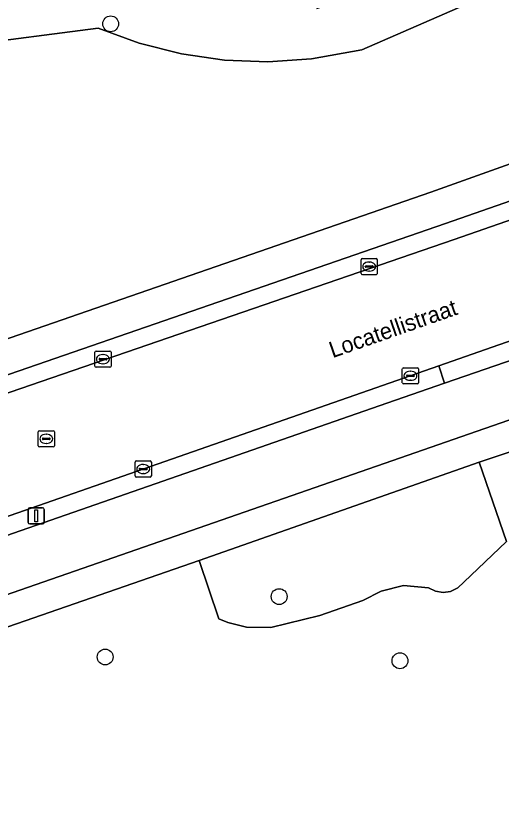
# Model space of a CAD drawing. Extents: x 159817 to 160765, y 380688 to 381638.
# Drawn here: x 160218.82 to 160248.8, y 380832.51 to 380881.05 of the extents above; entities that cross this region are included whole.
import ezdxf

# ---------------------------------------------------------------- set-up
doc = ezdxf.new("R2010")
doc.units = 0
for name, color, linetype in [('IMGEO_Berm_open', 7, 'Continuous'), ('IMGEO_Boom', 7, 'Continuous'), ('IMGEO_Fietspad_gesloten', 7, 'Continuous'), ('IMGEO_Groenvoorziening', 7, 'Continuous'), ('IMGEO_Kolk', 7, 'Continuous'), ('IMGEO_Lichtmast', 7, 'Continuous'), ('IMGEO_Openbare_ruimte_label', 7, 'Continuous'), ('IMGEO_Rijbaan_lokaal_gesloten', 7, 'Continuous'), ('IMGEO_Rioolput', 7, 'Continuous'), ('IMGEO_Voetpad_open', 7, 'Continuous')]:
    doc.layers.add(name, color=color, linetype=linetype)

msp = doc.modelspace()

# ---------------------------------------------------------------- linework, layer by layer
at = {"layer": 'IMGEO_Berm_open'}
for points in [[(160258.032, 380872.366), (160257.939, 380872.612), (160245.35, 380868.231), (160203.278, 380853.707)], [(160208.628, 380854.439), (160245.892, 380867.232), (160259.13, 380871.851)], [(160245.306, 380858.382), (160244.942, 380859.44), (160200.245, 380843.851), (160184.195, 380838.372)], [(160194.251, 380840.623), (160241.26, 380856.971), (160245.306, 380858.382)]]:
    msp.add_lwpolyline(points, dxfattribs=at)
msp.add_lwpolyline([(160252.766, 380860.95), (160252.421, 380862.048), (160244.942, 380859.44), (160245.306, 380858.382)], close=True, dxfattribs=at)
at = {"layer": 'IMGEO_Boom'}
for centre in [(160224.68, 380880.545), (160235.089, 380845.202), (160224.342, 380841.476), (160242.547, 380841.242)]:
    msp.add_circle(centre, 0.489, dxfattribs=at)
at = {"layer": 'IMGEO_Fietspad_gesloten'}
for points in [[(160312.936, 380882.064), (160310.27, 380881.1), (160252.914, 380861.001), (160252.766, 380860.95), (160245.306, 380858.382), (160241.26, 380856.971), (160194.251, 380840.623)], [(160185.448, 380834.002), (160214.797, 380844.116), (160254.484, 380857.89), (160313.244, 380878.473)], [(160257.134, 380874.691), (160244.449, 380870.167), (160212.621, 380859.165), (160209.034, 380857.925), (160202.886, 380855.8), (160196.659, 380853.844)], [(160203.278, 380853.707), (160245.35, 380868.231), (160257.939, 380872.612), (160258.032, 380872.366)]]:
    msp.add_lwpolyline(points, dxfattribs=at)
at = {"layer": 'IMGEO_Groenvoorziening'}
for points in [[(160218.084, 380882.815), (160206.489, 380872.61), (160215.634, 380879.207), (160223.918, 380880.278), (160226.441, 380879.35), (160229.047, 380878.691), (160231.708, 380878.307), (160234.394, 380878.204), (160237.076, 380878.383), (160240.184, 380878.949), (160253.758, 380884.876), (160253.17, 380886.647), (160237.384, 380881.476)], [(160253.758, 380884.876), (160240.184, 380878.949), (160237.076, 380878.383), (160234.394, 380878.204), (160231.708, 380878.307), (160229.047, 380878.691), (160226.441, 380879.35), (160223.918, 380880.278), (160215.634, 380879.207), (160206.489, 380872.61), (160205.888, 380872.081), (160204.881, 380871.517), (160202.436, 380868.022), (160202.535, 380866.772), (160203.004, 380864.973), (160203.836, 380863.311), (160204.996, 380861.858), (160206.432, 380860.678), (160208.082, 380859.822), (160209.874, 380859.328), (160212.621, 380859.165), (160244.449, 380870.167), (160257.134, 380874.691)], [(160254.028, 380855.706), (160247.431, 380853.502), (160249.122, 380848.609), (160246.491, 380846.097), (160246.127, 380845.74), (160245.678, 380845.514), (160245.207, 380845.446), (160244.739, 380845.527), (160244.318, 380845.749), (160242.759, 380845.884), (160241.397, 380845.541), (160240.251, 380844.964), (160237.598, 380844.027), (160234.579, 380843.289), (160233.078, 380843.305), (160231.909, 380843.599), (160231.354, 380843.836), (160230.145, 380847.428), (160187.08, 380832.509)]]:
    msp.add_lwpolyline(points, dxfattribs=at)
msp.add_lwpolyline([(160230.145, 380847.428), (160231.354, 380843.836), (160231.909, 380843.599), (160233.078, 380843.305), (160234.579, 380843.289), (160237.598, 380844.027), (160240.251, 380844.964), (160241.397, 380845.541), (160242.759, 380845.884), (160244.318, 380845.749), (160244.739, 380845.527), (160245.207, 380845.446), (160245.678, 380845.514), (160246.127, 380845.74), (160246.491, 380846.097), (160249.122, 380848.609), (160247.431, 380853.502)], close=True, dxfattribs=at)
at = {"layer": 'IMGEO_Kolk'}
for p, q in [((160240.149, 380865.142), (160240.149, 380865.994)), ((160240.224, 380866.068), (160241.076, 380866.068)), ((160241.15, 380865.994), (160241.15, 380865.142)), ((160240.408, 380865.562), (160240.408, 380865.574)), ((160240.846, 380865.525), (160240.448, 380865.525)), ((160240.451, 380865.611), (160240.849, 380865.611)), ((160240.637, 380865.848), (160240.662, 380865.848)), ((160240.892, 380865.574), (160240.892, 380865.562)), ((160241.076, 380865.068), (160240.224, 380865.068)), ((160240.66, 380865.288), (160240.635, 380865.288)), ((160223.703, 380859.427), (160223.703, 380860.279)), ((160223.778, 380860.353), (160224.63, 380860.353)), ((160224.191, 380860.133), (160224.216, 380860.133)), ((160224.704, 380860.279), (160224.704, 380859.427)), ((160223.962, 380859.847), (160223.962, 380859.859)), ((160224.4, 380859.81), (160224.002, 380859.81)), ((160224.005, 380859.896), (160224.403, 380859.896)), ((160224.446, 380859.859), (160224.446, 380859.847)), ((160224.63, 380859.353), (160223.778, 380859.353)), ((160224.214, 380859.573), (160224.189, 380859.573)), ((160242.694, 380858.403), (160242.694, 380859.255)), ((160242.769, 380859.329), (160243.621, 380859.329)), ((160243.695, 380859.255), (160243.695, 380858.403)), ((160242.953, 380858.823), (160242.953, 380858.835)), ((160243.391, 380858.786), (160242.993, 380858.786)), ((160242.996, 380858.872), (160243.394, 380858.872)), ((160243.182, 380859.109), (160243.207, 380859.109)), ((160243.437, 380858.835), (160243.437, 380858.823)), ((160243.621, 380858.329), (160242.769, 380858.329)), ((160243.205, 380858.549), (160243.18, 380858.549)), ((160226.193, 380852.648), (160226.193, 380853.5)), ((160226.268, 380853.574), (160227.12, 380853.574)), ((160226.681, 380853.354), (160226.706, 380853.354)), ((160227.194, 380853.5), (160227.194, 380852.648)), ((160226.452, 380853.068), (160226.452, 380853.08)), ((160226.89, 380853.031), (160226.492, 380853.031)), ((160226.495, 380853.117), (160226.893, 380853.117)), ((160226.936, 380853.08), (160226.936, 380853.068)), ((160227.12, 380852.574), (160226.268, 380852.574)), ((160226.704, 380852.794), (160226.679, 380852.794))]:
    msp.add_line(p, q, dxfattribs=at)
for points in [[(160240.149, 380865.142), (160240.149, 380865.994)], [(160240.224, 380866.068), (160241.076, 380866.068)], [(160241.15, 380865.994), (160241.15, 380865.142)], [(160241.076, 380865.068), (160240.224, 380865.068)], [(160223.703, 380859.427), (160223.703, 380860.279)], [(160223.778, 380860.353), (160224.63, 380860.353)], [(160224.704, 380860.279), (160224.704, 380859.427)], [(160224.63, 380859.353), (160223.778, 380859.353)], [(160242.694, 380858.403), (160242.694, 380859.255)], [(160242.769, 380859.329), (160243.621, 380859.329)], [(160243.695, 380859.255), (160243.695, 380858.403)], [(160243.621, 380858.329), (160242.769, 380858.329)], [(160226.193, 380852.648), (160226.193, 380853.5)], [(160226.268, 380853.574), (160227.12, 380853.574)], [(160227.194, 380853.5), (160227.194, 380852.648)], [(160227.12, 380852.574), (160226.268, 380852.574)]]:
    msp.add_lwpolyline(points, dxfattribs=at)
for centre, radius, start, end in [((160240.226, 380865.992), 0.0765, 91.552, 178.448), ((160240.226, 380865.992), 0.0765, 91.552, 178.448), ((160241.074, 380865.992), 0.0765, 1.552, 88.448), ((160241.074, 380865.992), 0.0765, 1.552, 88.448), ((160240.448, 380865.571), 0.0403, 85.8775, 175.7526), ((160240.445, 380865.561), 0.0366, 178.938, 274.7102), ((160240.849, 380865.568), 0.043, 264.8664, 352.4533), ((160240.853, 380865.573), 0.0386, 1.7309, 96.639), ((160240.226, 380865.144), 0.0765, 181.552, 268.448), ((160240.226, 380865.144), 0.0765, 181.552, 268.448), ((160241.074, 380865.144), 0.0765, 271.552, 358.448), ((160241.074, 380865.144), 0.0765, 271.552, 358.448), ((160223.78, 380860.277), 0.0765, 91.552, 178.448), ((160223.78, 380860.277), 0.0765, 91.552, 178.448), ((160224.628, 380860.277), 0.0765, 1.552, 88.448), ((160224.628, 380860.277), 0.0765, 1.552, 88.448), ((160224.002, 380859.856), 0.0403, 85.8775, 175.7526), ((160223.999, 380859.846), 0.0366, 178.938, 274.7102), ((160224.403, 380859.853), 0.043, 264.8664, 352.4533), ((160224.407, 380859.858), 0.0386, 1.7309, 96.639), ((160223.78, 380859.429), 0.0765, 181.552, 268.448), ((160223.78, 380859.429), 0.0765, 181.552, 268.448), ((160224.628, 380859.429), 0.0765, 271.552, 358.448), ((160224.628, 380859.429), 0.0765, 271.552, 358.448), ((160242.771, 380859.253), 0.0765, 91.552, 178.448), ((160242.771, 380859.253), 0.0765, 91.552, 178.448), ((160243.619, 380859.253), 0.0765, 1.552, 88.448), ((160243.619, 380859.253), 0.0765, 1.552, 88.448), ((160242.993, 380858.832), 0.0403, 85.8775, 175.7526), ((160242.99, 380858.822), 0.0366, 178.938, 274.7102), ((160243.394, 380858.829), 0.043, 264.8664, 352.4533), ((160243.398, 380858.834), 0.0386, 1.7309, 96.639), ((160242.771, 380858.405), 0.0765, 181.552, 268.448), ((160242.771, 380858.405), 0.0765, 181.552, 268.448), ((160243.619, 380858.405), 0.0765, 271.552, 358.448), ((160243.619, 380858.405), 0.0765, 271.552, 358.448), ((160226.27, 380853.498), 0.0765, 91.552, 178.448), ((160226.27, 380853.498), 0.0765, 91.552, 178.448), ((160227.118, 380853.498), 0.0765, 1.552, 88.448), ((160227.118, 380853.498), 0.0765, 1.552, 88.448), ((160226.492, 380853.077), 0.0403, 85.8775, 175.7526), ((160226.489, 380853.067), 0.0366, 178.938, 274.7102), ((160226.893, 380853.074), 0.043, 264.8664, 352.4533), ((160226.897, 380853.079), 0.0386, 1.7309, 96.639), ((160226.27, 380852.65), 0.0765, 181.552, 268.448), ((160226.27, 380852.65), 0.0765, 181.552, 268.448), ((160227.118, 380852.65), 0.0765, 271.552, 358.448), ((160227.118, 380852.65), 0.0765, 271.552, 358.448)]:
    msp.add_arc(centre, radius, start, end, dxfattribs=at)
for centre, major_axis, ratio, start_param, end_param in [((160240.636, 380865.568), (-0.387, 0.002), 0.722429, 4.712389, 7.853982), ((160240.661, 380865.568), (-0.39, 0.002), 0.717154, 1.570796, 4.712389), ((160224.19, 380859.853), (-0.387, 0.002), 0.722429, 4.712389, 7.853982), ((160224.215, 380859.853), (-0.39, 0.002), 0.717154, 1.570796, 4.712389), ((160243.181, 380858.829), (-0.387, 0.002), 0.722429, 4.712389, 7.853982), ((160243.206, 380858.829), (-0.39, 0.002), 0.717154, 1.570796, 4.712389), ((160226.68, 380853.074), (-0.387, 0.002), 0.722429, 4.712389, 7.853982), ((160226.705, 380853.074), (-0.39, 0.002), 0.717154, 1.570796, 4.712389)]:
    msp.add_ellipse(centre, major_axis=major_axis, ratio=ratio, start_param=start_param, end_param=end_param, dxfattribs=at)
at = {"layer": 'IMGEO_Lichtmast'}
for p, q in [((160219.588, 380849.782), (160219.588, 380850.582)), ((160219.588, 380850.582), (160219.588, 380849.782)), ((160219.688, 380850.682), (160220.478, 380850.682)), ((160220.478, 380850.682), (160219.688, 380850.682)), ((160220.578, 380850.582), (160220.578, 380849.782)), ((160220.578, 380849.782), (160220.578, 380850.582)), ((160220.478, 380849.682), (160219.688, 380849.682)), ((160219.688, 380849.682), (160220.478, 380849.682))]:
    msp.add_line(p, q, dxfattribs=at)
msp.add_lwpolyline([(160220.008, 380850.557), (160220.158, 380850.557), (160220.158, 380849.807), (160220.008, 380849.807), (160220.008, 380850.557)], dxfattribs=at)
for centre, start, end in [((160219.688, 380850.582), 90, 180), ((160219.688, 380850.582), 90, 180), ((160220.478, 380850.582), 0, 90), ((160220.478, 380850.582), 360, 90), ((160219.688, 380849.782), 180, 270), ((160219.688, 380849.782), 180, 270), ((160220.478, 380849.782), 270, 0), ((160220.478, 380849.782), 270, 0)]:
    msp.add_arc(centre, 0.1, start, end, dxfattribs=at)
at = {"layer": 'IMGEO_Rijbaan_lokaal_gesloten'}
for points in [[(160184.195, 380838.372), (160200.245, 380843.851), (160244.942, 380859.44), (160252.421, 380862.048), (160260.803, 380864.969), (160276.576, 380870.51), (160275.105, 380874.334), (160273.637, 380878.149)], [(160259.13, 380871.851), (160245.892, 380867.232), (160208.628, 380854.439)]]:
    msp.add_lwpolyline(points, dxfattribs=at)
at = {"layer": 'IMGEO_Rioolput'}
for p, q in [((160220.205, 380854.51), (160220.205, 380855.362)), ((160220.28, 380855.436), (160221.132, 380855.436)), ((160221.206, 380855.362), (160221.206, 380854.51)), ((160220.464, 380854.93), (160220.464, 380854.942)), ((160220.902, 380854.893), (160220.504, 380854.893)), ((160220.507, 380854.979), (160220.905, 380854.979)), ((160220.693, 380855.216), (160220.718, 380855.216)), ((160220.948, 380854.942), (160220.948, 380854.93)), ((160221.132, 380854.436), (160220.28, 380854.436)), ((160220.716, 380854.656), (160220.691, 380854.656))]:
    msp.add_line(p, q, dxfattribs=at)
for points in [[(160220.205, 380854.51), (160220.205, 380855.362)], [(160220.28, 380855.436), (160221.132, 380855.436)], [(160221.206, 380855.362), (160221.206, 380854.51)], [(160221.132, 380854.436), (160220.28, 380854.436)]]:
    msp.add_lwpolyline(points, dxfattribs=at)
for centre, radius, start, end in [((160220.282, 380855.36), 0.0765, 91.552, 178.448), ((160220.282, 380855.36), 0.0765, 91.552, 178.448), ((160221.13, 380855.36), 0.0765, 1.552, 88.448), ((160221.13, 380855.36), 0.0765, 1.552, 88.448), ((160220.504, 380854.939), 0.0403, 85.8775, 175.7526), ((160220.501, 380854.929), 0.0366, 178.938, 274.7102), ((160220.905, 380854.936), 0.043, 264.8664, 352.4533), ((160220.909, 380854.941), 0.0386, 1.7309, 96.639), ((160220.282, 380854.512), 0.0765, 181.552, 268.448), ((160220.282, 380854.512), 0.0765, 181.552, 268.448), ((160221.13, 380854.512), 0.0765, 271.552, 358.448), ((160221.13, 380854.512), 0.0765, 271.552, 358.448)]:
    msp.add_arc(centre, radius, start, end, dxfattribs=at)
for centre, major_axis, ratio, start_param, end_param in [((160220.692, 380854.936), (-0.387, 0.002), 0.722429, 4.712389, 7.853982), ((160220.717, 380854.936), (-0.39, 0.002), 0.717154, 1.570796, 4.712389)]:
    msp.add_ellipse(centre, major_axis=major_axis, ratio=ratio, start_param=start_param, end_param=end_param, dxfattribs=at)
at = {"layer": 'IMGEO_Voetpad_open'}
for points in [[(160313.244, 380878.473), (160254.484, 380857.89), (160214.797, 380844.116), (160185.448, 380834.002)], [(160187.08, 380832.509), (160230.145, 380847.428), (160247.431, 380853.502), (160254.028, 380855.706), (160291.864, 380868.941), (160313.867, 380876.638)]]:
    msp.add_lwpolyline(points, dxfattribs=at)

# ---------------------------------------------------------------- texts
at = {"layer": 'IMGEO_Openbare_ruimte_label'}
msp.add_text('Locatellistraat', height=1, rotation=19.2143, dxfattribs=at).set_placement((160238.386, 380859.913))

doc.saveas('drawing.dxf')
